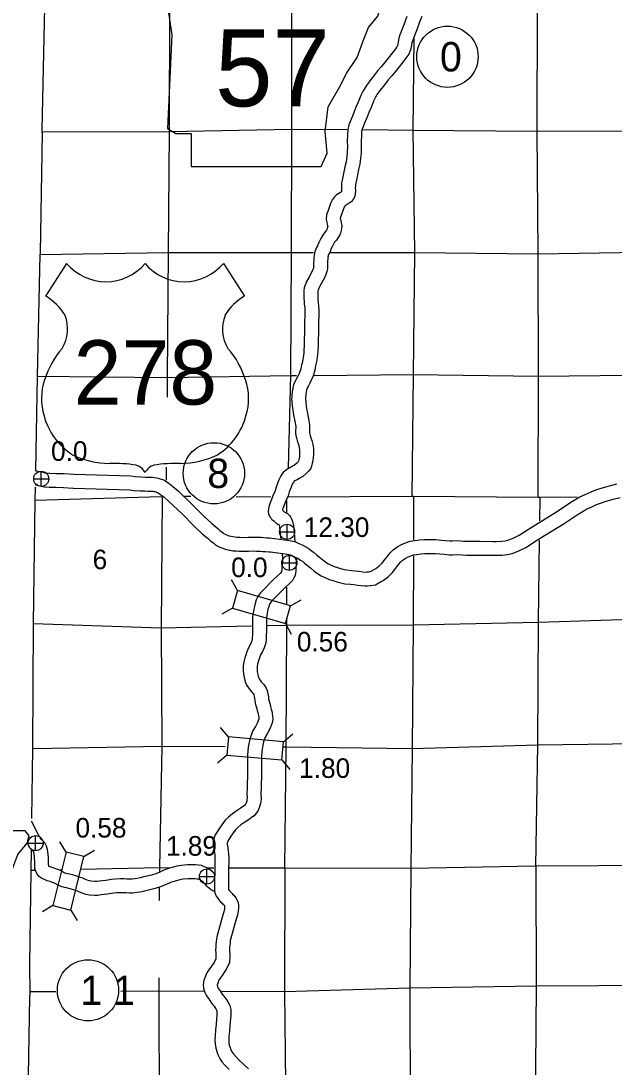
# Model space of a CAD drawing. Extents: x 369523 to 838377, y 495025 to 936819.
# Drawn here: x 574457 to 600020, y 546526 to 591641 of the extents above; entities that cross this region are included whole.
import ezdxf

# ---------------------------------------------------------------- set-up
doc = ezdxf.new("R2010")
doc.units = 0
for name, color, linetype in [('22', 7, 'Continuous'), ('6', 7, 'Continuous'), ('DSN_BRDG_Annotation', 7, 'Continuous'), ('DSN_DRFT_Common-Annotations', 7, 'Continuous'), ('DSN_DRFT_Common-Line', 7, 'Continuous'), ('DSN_DRFT_Junk-No-Plot', 7, 'Continuous'), ('Level 1', 7, 'Continuous'), ('Level 11', 7, 'Continuous'), ('Level 15', 7, 'Continuous'), ('Level 21', 7, 'Continuous'), ('Level 22', 7, 'Continuous'), ('Level 6', 7, 'Continuous')]:
    doc.layers.add(name, color=color, linetype=linetype)

msp = doc.modelspace()

# ---------------------------------------------------------------- linework, layer by layer
at = {"layer": '22'}
for points in [[(580555, 593710), (580954, 591045), (580777, 587004), (581132, 586782), (581798, 586782), (581798, 585361), (587394, 585361), (587660, 585938), (587571, 586871), (587704, 587937), (588193, 588780), (588504, 589402), (588948, 590068), (589214, 590779), (589436, 591356), (589836, 591845), (589925, 592155), (589747, 592377), (588371, 592377), (588681, 592999), (588726, 593399), (588542, 593706)], [(565448, 558052), (565848, 555387), (565670, 551346), (566025, 551124), (566691, 551124), (566691, 549703), (572287, 549703), (572554, 550280), (572465, 551213), (572598, 552279), (573086, 553122), (573397, 553744), (573841, 554410), (574108, 555121), (574330, 555698), (574730, 556187), (574818, 556498), (574641, 556720), (573264, 556720), (573575, 557341), (573619, 557741), (573435, 558048)]]:
    msp.add_lwpolyline(points, close=True, dxfattribs=at)
at = {"layer": '6'}
for p, q in [((576428, 581182), (575519, 579777)), ((583184, 581182), (584093, 579777))]:
    msp.add_line(p, q, dxfattribs=at)
for centre, radius, start, end in [((578120, 582606), 2211, 220.075, 319.6701), ((581492, 582606), 2211, 220.3299, 319.925), ((574332, 577737), 2361, 30.7809, 59.9883), ((585280, 577737), 2361, 120.0117, 149.2191), ((574852, 578359), 1618, 328.8105, 21.2108), ((584761, 578359), 1618, 158.7892, 211.1895), ((579084, 575042), 3776, 138.9565, 162.6913), ((580529, 575042), 3776, 17.3087, 41.0435), ((577837, 575351), 2495, 160.9576, 197.3819), ((581775, 575351), 2495, 342.6181, 19.0424), ((578243, 575358), 2887, 195.1074, 237.1312), ((581369, 575358), 2887, 302.8688, 344.8926), ((578297, 576267), 3707, 244.0771, 269.5779), ((578383, 565772), 6790, 81.1942, 90.9539), ((581230, 565772), 6790, 89.0461, 98.8058), ((581315, 576267), 3707, 270.4221, 295.9229), ((579232, 571860), 651, 28.0342, 72.9864), ((580381, 571860), 651, 107.0136, 151.9658)]:
    msp.add_arc(centre, radius, start, end, dxfattribs=at)
at = {"layer": 'DSN_DRFT_Common-Annotations'}
for p, q in [((575333, 571567), (575333, 572217)), ((575008, 571892), (575658, 571892)), ((585928, 569283), (585928, 569933)), ((585603, 569608), (586253, 569608)), ((586025, 567943), (586025, 568593)), ((585700, 568268), (586350, 568268)), ((575092, 555860), (575092, 556510)), ((574767, 556185), (575417, 556185)), ((582475, 554421), (582475, 555071)), ((582150, 554746), (582800, 554746))]:
    msp.add_line(p, q, dxfattribs=at)
for centre in [(575333, 571892), (585928, 569608), (586025, 568268), (575092, 556185), (582475, 554746)]:
    msp.add_circle(centre, 325, dxfattribs=at)
at = {"layer": 'DSN_DRFT_Common-Line'}
for centre in [(592840, 590097), (582773, 572133), (577347, 549836)]:
    msp.add_circle(centre, 1320, dxfattribs=at)
at = {"layer": 'Level 1'}
for points in [[(591087, 591834), (590957, 591469), (590873, 591264), (590826, 591147), (590785, 591037), (590743, 590894), (590723, 590809), (590694, 590645), (590680, 590587), (590666, 590544), (590649, 590511), (590602, 590439), (590342, 590108), (590113, 589814), (589989, 589663), (589824, 589483), (589612, 589202), (589451, 589002), (589315, 588819), (589204, 588632), (589105, 588421), (588991, 588140), (588898, 587923), (588804, 587686), (588741, 587534), (588595, 587164), (588545, 586964), (588530, 586738), (588519, 586449), (588526, 586227), (588520, 585988), (588501, 585797), (588468, 585571), (588423, 585346), (588380, 585129), (588330, 584919), (588296, 584773), (588279, 584655), (588270, 584555), (588268, 584433), (588274, 584339), (588272, 584305), (588271, 584292), (588268, 584272), (588234, 584249), (588064, 584142), (587967, 584054), (587880, 583938), (587802, 583765), (587692, 583460), (587666, 583396), (587627, 583297), (587619, 583080), (587637, 582960), (587661, 582879), (587672, 582825), (587681, 582774), (587681, 582771), (587676, 582754), (587656, 582684), (587652, 582674), (587620, 582617), (587578, 582555), (587476, 582434), (587383, 582259), (587324, 582144)], [(591730, 591832), (591649, 591625), (591518, 591255), (591429, 591038), (591386, 590931), (591355, 590847), (591323, 590741), (591311, 590690), (591282, 590521), (591257, 590423), (591224, 590317), (591169, 590210), (591090, 590088), (590814, 589738), (590582, 589441), (590443, 589270), (590286, 589099), (590085, 588833), (589925, 588634), (589815, 588486), (589735, 588352), (589656, 588181), (589545, 587908), (589453, 587694), (589361, 587462), (589298, 587309), (589167, 586979), (589140, 586870), (589129, 586707), (589119, 586447), (589126, 586229), (589119, 585950), (589097, 585724), (589060, 585469), (589012, 585228), (588966, 585000), (588914, 584781), (588886, 584662), (588875, 584587), (588870, 584523), (588868, 584448), (588876, 584338), (588870, 584263), (588868, 584225), (588856, 584147), (588833, 584061), (588791, 583956), (588692, 583837), (588567, 583749), (588427, 583661), (588412, 583648), (588400, 583632), (588359, 583540), (588252, 583246), (588223, 583174), (588223, 583172), (588221, 583113), (588224, 583092), (588244, 583025), (588262, 582935), (588282, 582818), (588279, 582692), (588256, 582597), (588225, 582494), (588198, 582420), (588131, 582301), (588057, 582193), (587976, 582096), (587915, 581982), (587859, 581872)], [(587321, 582136), (587269, 582027), (587234, 581945), (587198, 581870), (587164, 581798), (587128, 581700), (587108, 581614), (587094, 581533), (587082, 581430), (587074, 581328), (587070, 581202), (587073, 581099), (587075, 581048), (587073, 581029), (587065, 580983), (587043, 580921), (587023, 580874), (586955, 580744), (586890, 580625), (586808, 580478), (586770, 580402), (586730, 580318), (586691, 580218), (586666, 580124), (586651, 580019), (586651, 579920), (586650, 579866), (586650, 579779), (586653, 579675), (586658, 579556), (586670, 579420), (586692, 579279), (586699, 579177), (586676, 578430), (586664, 577660), (586654, 577414), (586646, 577331), (586633, 577230), (586614, 577128), (586601, 577041), (586571, 576889), (586554, 576807), (586535, 576725), (586514, 576644), (586485, 576549), (586467, 576483), (586445, 576431), (586371, 576293), (586304, 576160), (586269, 576080), (586205, 575946), (586189, 575890), (586157, 575727), (586146, 575632), (586135, 575541), (586129, 575445), (586125, 575334), (586130, 575225), (586133, 575187), (586142, 575104), (586151, 575023), (586157, 574966), (586173, 574827), (586199, 574675), (586223, 574572), (586251, 574446), (586271, 574311), (586286, 574224), (586298, 574155), (586298, 574105), (586291, 573967), (586294, 573866), (586312, 573761), (586347, 573610), (586384, 573492), (586417, 573380), (586452, 573252), (586464, 573160), (586466, 573079), (586461, 572980), (586456, 572855), (586449, 572785), (586430, 572713), (586415, 572651), (586407, 572627), (586398, 572615), (586348, 572566), (586254, 572486), (586168, 572435), (586077, 572381), (585966, 572328), (585840, 572243), (585761, 572163), (585656, 572023), (585574, 571855), (585534, 571740), (585458, 571531), (585408, 571383), (585313, 571165), (585166, 570776), (585146, 570673)], [(587863, 581880), (587816, 581780), (587780, 581697), (587741, 581615), (587719, 581567), (587704, 581528), (587696, 581494), (587688, 581447), (587680, 581373), (587673, 581294), (587670, 581201), (587673, 581118), (587676, 581038), (587670, 580953), (587647, 580830), (587602, 580699), (587563, 580613), (587484, 580462), (587415, 580335), (587338, 580197), (587309, 580140), (587281, 580080), (587262, 580031), (587255, 580005), (587251, 579977), (587251, 579912), (587250, 579858), (587250, 579789), (587253, 579696), (587257, 579595), (587266, 579494), (587289, 579347), (587300, 579188), (587276, 578416), (587264, 577643), (587253, 577372), (587242, 577262), (587225, 577135), (587205, 577028), (587192, 576938), (587159, 576773), (587141, 576679), (587117, 576580), (587091, 576481), (587061, 576383), (587036, 576288), (586987, 576172), (586903, 576016), (586847, 575904), (586815, 575831), (586770, 575737), (586750, 575634), (586742, 575564), (586733, 575487), (586728, 575415), (586726, 575338), (586729, 575262), (586731, 575240), (586739, 575167), (586747, 575088), (586753, 575033), (586767, 574911), (586787, 574794), (586808, 574706), (586841, 574555), (586863, 574406), (586877, 574329), (586898, 574209), (586899, 574091), (586892, 573961), (586893, 573925), (586900, 573879), (586926, 573769), (586958, 573667), (586995, 573543), (587042, 573371), (587063, 573207), (587067, 573071), (587061, 572954), (587055, 572810), (587040, 572676), (587012, 572567), (586992, 572485), (586945, 572344), (586850, 572219), (586753, 572123), (586604, 571997), (586474, 571919), (586358, 571851), (586265, 571806), (586225, 571779), (586216, 571770), (586170, 571709), (586129, 571623), (586099, 571538), (586024, 571333), (585968, 571167), (585870, 570939), (585745, 570610), (585734, 570556)], [(585147, 570681), (585130, 570603), (585119, 570496), (585133, 570370), (585203, 570241), (585235, 570196), (585275, 570143), (585351, 570076), (585445, 569995), (585526, 569944), (585570, 569919), (585583, 569900), (585589, 569883), (585601, 569827), (585607, 569789), (585617, 569698), (585655, 569296)], [(585732, 570548), (585731, 570541), (585744, 570529), (585803, 570478), (585835, 570458), (585893, 570425), (585943, 570393), (586023, 570322), (586068, 570254), (586120, 570175), (586166, 570053), (586191, 569936), (586202, 569866), (586214, 569757), (586268, 569186)], [(585710, 568673), (585730, 568425), (585725, 568365), (585724, 568288), (585715, 568208), (585705, 568090), (585702, 567983), (585694, 567905), (585682, 567882), (585675, 567870), (585643, 567833), (585353, 567561), (584848, 567048), (584787, 566976), (584691, 566861), (584635, 566763), (584601, 566669), (584569, 566572), (584517, 566392), (584497, 566269), (584470, 566108), (584444, 565948), (584437, 565831), (584440, 565675), (584441, 565507), (584434, 565331), (584433, 565167), (584430, 565020), (584423, 564948), (584382, 564833), (584322, 564707), (584242, 564547), (584179, 564395), (584144, 564294), (584100, 564172), (584064, 564006), (584041, 563848), (584035, 563614), (584051, 563482), (584074, 563337), (584107, 563199), (584140, 563106), (584200, 562979), (584267, 562876), (584336, 562774), (584416, 562684), (584459, 562641), (584460, 562640), (584488, 562593), (584501, 562566), (584514, 562513), (584524, 562430), (584536, 562324), (584565, 562166), (584607, 562026), (584643, 561908), (584666, 561824), (584681, 561754), (584694, 561679), (584708, 561596), (584709, 561550), (584707, 561536), (584646, 561386), (584563, 561220), (584437, 561010), (584340, 560716), (584298, 560544), (584255, 560327), (584226, 559992), (584224, 559688), (584226, 559381), (584219, 559081), (584213, 558720), (584209, 558545), (584197, 558345), (584206, 558122), (584199, 558063), (584187, 557997), (584178, 557950), (584151, 557880), (584138, 557862), (584096, 557811), (584046, 557776), (583913, 557675), (583776, 557589), (583577, 557447), (583405, 557309), (583264, 557176), (583113, 556972), (583011, 556822), (582910, 556667), (582832, 556539), (582772, 556384), (582749, 556254), (582747, 556117), (582764, 555970), (582787, 555865), (582800, 555770), (582811, 555672), (582817, 555501)], [(586328, 568476), (586331, 568426), (586325, 568337), (586323, 568251), (586313, 568150), (586304, 568055), (586301, 567942), (586286, 567804), (586262, 567702), (586207, 567589), (586159, 567512), (586076, 567417), (585772, 567132), (585290, 566642), (585244, 566588), (585186, 566518), (585182, 566512), (585168, 566473), (585142, 566394), (585103, 566260), (585089, 566171), (585062, 566011), (585041, 565882), (585037, 565819), (585040, 565682), (585041, 565497), (585034, 565317), (585033, 565159), (585029, 564986), (585013, 564817), (584937, 564603), (584862, 564444), (584788, 564298), (584740, 564181), (584709, 564093), (584678, 564007), (584655, 563899), (584640, 563797), (584636, 563642), (584645, 563566), (584663, 563454), (584684, 563368), (584696, 563334), (584725, 563272), (584767, 563207), (584811, 563142), (584851, 563097), (584905, 563044), (584952, 562985), (585021, 562872), (585069, 562764), (585105, 562624), (585120, 562499), (585130, 562412), (585149, 562307), (585181, 562199), (585219, 562076), (585249, 561968), (585270, 561870), (585286, 561777), (585306, 561652), (585310, 561513), (585289, 561375), (585192, 561139), (585089, 560931), (584986, 560759), (584917, 560552), (584884, 560415), (584850, 560242), (584826, 559964), (584824, 559687), (584826, 559376), (584819, 559070), (584813, 558707), (584808, 558520), (584798, 558340), (584808, 558097), (584792, 557972), (584777, 557889), (584758, 557788), (584683, 557589), (584612, 557494), (584507, 557365), (584398, 557290), (584256, 557181), (584110, 557089), (583939, 556968), (583800, 556856), (583714, 556776), (583603, 556625), (583510, 556489), (583417, 556347), (583372, 556273), (583353, 556224), (583349, 556197), (583348, 556146), (583357, 556069), (583378, 555969), (583395, 555844), (583409, 555717), (583417, 555524)], [(582794, 554863), (582718, 554941), (582576, 555056), (582443, 555131), (582363, 555167), (582239, 555212), (582109, 555232), (581978, 555241), (581629, 555241), (581380, 555226), (581174, 555194), (581036, 555153), (580860, 555099), (580694, 555040), (580593, 555000), (580439, 554932), (580272, 554865), (580078, 554804), (579756, 554727), (579597, 554691), (579467, 554663), (579368, 554643), (579246, 554628), (579156, 554629), (579020, 554636), (578907, 554641), (578744, 554643), (578527, 554635), (578365, 554616), (578113, 554576), (577975, 554560), (577846, 554543), (577732, 554530), (577644, 554528), (577490, 554537), (577409, 554555), (577309, 554584), (577236, 554616), (577129, 554667), (577014, 554706), (576915, 554738), (576866, 554755), (576684, 554810), (576552, 554842), (576466, 554860), (576406, 554875), (576350, 554894), (576304, 554917), (576296, 554922), (576223, 554968), (576088, 555030), (575963, 555076), (575890, 555097), (575802, 555127), (575723, 555158), (575667, 555180), (575663, 555183), (575655, 555210), (575650, 555282), (575651, 555375), (575648, 555557), (575635, 555699), (575616, 555830), (575596, 555915), (575582, 555959), (575554, 556058), (575486, 556190), (575410, 556265), (575338, 556344), (575293, 556406), (575240, 556492), (575211, 556538), (574908, 557135)], [(582804, 554097), (582713, 554138), (582655, 554175), (582580, 554226), (582529, 554268), (582469, 554325), (582413, 554393), (582312, 554498), (582238, 554558), (582174, 554594), (582138, 554610), (582089, 554628), (582043, 554635), (581958, 554641), (581647, 554641), (581444, 554629), (581306, 554607), (581208, 554578), (581049, 554530), (580907, 554479), (580824, 554446), (580671, 554379), (580474, 554300), (580238, 554226), (579893, 554143), (579727, 554105), (579590, 554076), (579465, 554050), (579279, 554027), (579137, 554029), (578989, 554036), (578890, 554041), (578753, 554042), (578573, 554036), (578447, 554021), (578195, 553982), (578049, 553964), (577919, 553947), (577773, 553931), (577633, 553928), (577407, 553941), (577260, 553973), (577103, 554019), (576987, 554070), (576902, 554110), (576824, 554137), (576727, 554169), (576683, 554183), (576525, 554231), (576420, 554257), (576334, 554275), (576238, 554299), (576118, 554339), (576015, 554391), (575983, 554410), (575936, 554439), (575858, 554476), (575778, 554505), (575711, 554524), (575595, 554564), (575501, 554600), (575400, 554641), (575321, 554688), (575248, 554739), (575152, 554848), (575100, 554971), (575062, 555103), (575050, 555263), (575051, 555374), (575048, 555525), (575039, 555628), (575026, 555717), (575017, 555755), (575007, 555787), (574995, 555832), (574976, 555850), (574911, 555922)], [(582817, 555517), (582814, 555318), (582807, 555177), (582800, 554355), (582801, 554109), (582825, 554016), (582873, 553892), (582922, 553822), (582988, 553739), (583063, 553653), (583123, 553595), (583161, 553552), (583199, 553517), (583224, 553488), (583233, 553465), (583234, 553458), (583235, 553414), (583235, 553404), (583231, 553356), (583203, 553215), (583148, 553027), (582896, 552141), (582885, 552052), (582872, 551930), (582860, 551832), (582853, 551752), (582851, 551691), (582845, 551575), (582851, 551460), (582861, 551375), (582861, 551367), (582863, 551320), (582860, 551250), (582854, 551189)], [(583417, 555508), (583414, 555298), (583407, 555159), (583400, 554354), (583401, 554191), (583406, 554177), (583448, 554125), (583498, 554067), (583559, 554009), (583594, 553969), (583632, 553933), (583674, 553884), (583740, 553815), (583816, 553620), (583832, 553512), (583835, 553427), (583835, 553377), (583825, 553269), (583786, 553073), (583724, 552860), (583486, 552023), (583481, 551984), (583468, 551861), (583457, 551770), (583452, 551718), (583451, 551667), (583446, 551575), (583449, 551509), (583461, 551410), (583461, 551382), (583463, 551321), (583459, 551207), (583451, 551127), (583443, 551038)], [(582853, 551188), (582783, 551033), (582742, 550977), (582671, 550872), (582562, 550726), (582472, 550589), (582407, 550450), (582386, 550377), (582344, 550273), (582325, 550171), (582317, 550072), (582327, 549935), (582354, 549827), (582386, 549738), (582438, 549622), (582477, 549555), (582554, 549465), (582640, 549326), (582730, 549212), (582787, 549150), (582828, 549087), (582859, 549039), (582891, 548976), (582902, 548934), (582900, 548788), (582867, 548370), (582842, 548135), (582824, 547873), (582820, 547721), (582824, 547527), (582850, 547343), (582908, 547158), (582947, 547067), (583025, 546900), (583119, 546752), (583274, 546579), (583427, 546421)], [(583442, 551037), (583304, 550729), (583232, 550631), (583160, 550525), (583053, 550381), (582997, 550296), (582971, 550240), (582954, 550181), (582922, 550102), (582920, 550091), (582919, 550071), (582922, 550031), (582929, 550002), (582943, 549962), (582971, 549901), (583041, 549819), (583132, 549671), (583187, 549602), (583264, 549518), (583332, 549412), (583380, 549339), (583456, 549188), (583503, 549005), (583500, 548761), (583465, 548315), (583440, 548082), (583424, 547844), (583420, 547719), (583423, 547576), (583438, 547475), (583472, 547366), (583495, 547312), (583553, 547189), (583600, 547115), (583713, 546988), (583852, 546845), (584070, 546631), (584262, 546456)]]:
    msp.add_lwpolyline(points, dxfattribs=at)
at = {"layer": 'Level 11'}
for points in [[(575066, 572254), (575120, 572244), (575201, 572231), (575372, 572193), (575487, 572156), (575538, 572148), (575699, 572135), (575966, 572129), (576313, 572125), (576752, 572097)], [(576742, 572097), (579197, 572021), (579382, 571995), (579637, 571978), (579824, 571971), (579934, 571966), (580023, 571967), (580124, 571963), (580210, 571956), (580301, 571943), (580371, 571925), (580460, 571901), (580572, 571861), (580658, 571817), (580750, 571760), (580846, 571693), (580994, 571581), (581244, 571359), (581810, 570822), (582347, 570281), (582667, 569981), (582857, 569826), (582944, 569749), (583032, 569671), (583124, 569599), (583186, 569549), (583221, 569526), (583285, 569493), (583367, 569459), (583420, 569440), (583519, 569418), (583671, 569390), (583768, 569381), (583892, 569378), (584018, 569371), (584245, 569380), (584438, 569382), (584623, 569381), (584809, 569373), (584926, 569363), (585039, 569354), (585177, 569343), (585275, 569337), (585386, 569325), (586029, 569240)], [(575079, 571643), (575089, 571641), (575217, 571613), (575345, 571572), (575462, 571552), (575669, 571535), (575957, 571529), (576290, 571526), (576713, 571498)], [(586026, 569241), (586171, 569210), (586251, 569187), (586354, 569145), (586436, 569106), (586571, 569045), (586701, 568974), (586831, 568898), (586964, 568809), (587060, 568729), (587197, 568620), (587326, 568509), (587464, 568394), (587582, 568309), (587687, 568241), (587805, 568184), (587961, 568120), (588095, 568073), (588236, 568029), (588385, 567989), (588510, 567963), (588717, 567942), (588869, 567926), (589035, 567905), (589192, 567886), (589290, 567876), (589364, 567881), (589455, 567885), (589516, 567897), (589646, 567974), (589757, 568026), (589901, 568140), (590021, 568257), (590143, 568410), (590235, 568525), (590368, 568696), (590498, 568828), (590707, 568978), (590861, 569056), (591037, 569134), (591233, 569200), (591433, 569231), (591631, 569262), (591841, 569275), (592096, 569278), (592337, 569278), (592575, 569251), (592745, 569237), (592946, 569223), (593046, 569222), (593277, 569234), (593531, 569209), (593679, 569199), (593991, 569199), (594246, 569209), (594789, 569198), (594955, 569197), (595165, 569204), (595323, 569218), (595440, 569249), (595598, 569308), (595673, 569340), (595925, 569462), (596451, 569798), (597546, 570472), (598157, 570881), (598547, 571119), (598781, 571224), (599037, 571340), (599239, 571413), (599462, 571485), (599830, 571592), (600144, 571672)], [(576723, 571497), (579146, 571423), (579321, 571398), (579606, 571379), (579800, 571372), (579922, 571366), (580013, 571367), (580088, 571364), (580142, 571359), (580184, 571353), (580221, 571344), (580281, 571328), (580333, 571309), (580364, 571294), (580420, 571259), (580493, 571208), (580614, 571116), (580838, 570917), (581391, 570393), (581929, 569851), (582272, 569529), (582468, 569370), (582546, 569300), (582647, 569210), (582752, 569128), (582831, 569066), (582913, 569010), (583033, 568948), (583152, 568899), (583255, 568862), (583400, 568830), (583589, 568795), (583732, 568782), (583868, 568778), (584014, 568771), (584259, 568780), (584438, 568782), (584610, 568781), (584772, 568774), (584876, 568765), (584991, 568756), (585136, 568744), (585223, 568739), (585312, 568729), (585950, 568645)], [(585926, 568649), (586024, 568628), (586053, 568620), (586114, 568595), (586185, 568562), (586303, 568508), (586405, 568452), (586512, 568390), (586604, 568328), (586681, 568264), (586813, 568158), (586938, 568051), (587097, 567919), (587244, 567813), (587392, 567718), (587559, 567636), (587748, 567559), (587907, 567503), (588070, 567452), (588246, 567406), (588418, 567369), (588655, 567345), (588800, 567330), (588961, 567310), (589125, 567290), (589279, 567274), (589397, 567282), (589527, 567287), (589733, 567329), (589926, 567443), (590075, 567512), (590297, 567689), (590467, 567854), (590612, 568036), (590706, 568154), (590820, 568301), (590889, 568370), (591019, 568463), (591119, 568514), (591255, 568575), (591375, 568615), (591526, 568638), (591696, 568665), (591863, 568675), (592099, 568678), (592303, 568678), (592517, 568654), (592699, 568639), (592922, 568623), (593058, 568622), (593264, 568632), (593482, 568611), (593658, 568599), (594002, 568599), (594251, 568609), (594781, 568598), (594963, 568597), (595201, 568605), (595427, 568625), (595622, 568676), (595819, 568751), (595920, 568793), (596219, 568938), (596769, 569290), (597871, 569967), (598480, 570375), (598827, 570587), (599028, 570677), (599264, 570784), (599433, 570845), (599638, 570912), (599988, 571013), (600286, 571089)]]:
    msp.add_lwpolyline(points, dxfattribs=at)
at = {"layer": 'Level 15'}
for points in [[(580520, 571122), (575060, 570958)], [(581785, 571133), (581511, 571135)], [(585229, 571106), (583738, 571118)], [(598434, 571106), (596831, 571088), (596747, 571094), (591383, 571130), (591311, 571132), (585972, 571101)]]:
    msp.add_lwpolyline(points, dxfattribs=at)
at = {"layer": 'Level 21'}
for p, q in [((583790, 567077), (583535, 567540)), ((586073, 566419), (586535, 566675)), ((583571, 566316), (583109, 566061)), ((585854, 565658), (586109, 565196)), ((583401, 560761), (583061, 561165)), ((585768, 560558), (586172, 560898)), ((583333, 559972), (582929, 559632)), ((585701, 559769), (586041, 559365)), ((576407, 555793), (576134, 556246)), ((577175, 555603), (577628, 555875)), ((575834, 553488), (575382, 553215)), ((576603, 553297), (576875, 552844))]:
    msp.add_line(p, q, dxfattribs=at)
for points in [[(586073, 566419), (583790, 567077), (583571, 566316), (585854, 565658)], [(583333, 559972), (585701, 559769), (585768, 560558), (583401, 560761)], [(576603, 553297), (577175, 555603), (576407, 555793), (575834, 553488)]]:
    msp.add_lwpolyline(points, close=True, dxfattribs=at)
at = {"layer": 'Level 22'}
for points in [[(580858, 597511), (580863, 592205), (580846, 586878), (580805, 581651), (580764, 576264), (580754, 575409)], [(585986, 572369), (586083, 576346), (586119, 581651), (586131, 586979), (586129, 592262), (586193, 597512)], [(596747, 571094), (596757, 576326), (596745, 581591), (596707, 586889), (596719, 592176), (596719, 597546)], [(591395, 590889), (591353, 586932), (591413, 581648), (591363, 576395), (591311, 571132)], [(580846, 586878), (586131, 586979), (588499, 586958)], [(589185, 586952), (591353, 586932), (596707, 586889), (601999, 586904), (607544, 587007)], [(575350, 586852), (580846, 586878)], [(575288, 581567), (580805, 581651)], [(580805, 581651), (586119, 581651), (587071, 581650)], [(587785, 581650), (591413, 581648), (596745, 581591), (602035, 581680), (607517, 581710)], [(575161, 576318), (580764, 576264), (586083, 576346), (586327, 576348)], [(587100, 576355), (591363, 576395), (596757, 576326), (602071, 576382), (607489, 576436)], [(580717, 572390), (580710, 571831)], [(580543, 571123), (580507, 565465), (580525, 560365), (580424, 555112)], [(585912, 570446), (585912, 570956)], [(591383, 571130), (591376, 569265)], [(596819, 570080), (596831, 571088)], [(596644, 555197), (596732, 560424), (596766, 565719), (596809, 569249)], [(591373, 568580), (591361, 565603), (591325, 560264), (591267, 555083)], [(585918, 566481), (585917, 567224)], [(585087, 565567), (585919, 565585), (591361, 565603), (596766, 565719), (602141, 565881), (607311, 565847)], [(585826, 555104), (585895, 560330), (585919, 565585), (585918, 565854)], [(574979, 565662), (580507, 565465)], [(580507, 565465), (584401, 565552)], [(574979, 560270), (580525, 560365)], [(580525, 560365), (583254, 560347)], [(585761, 560331), (585895, 560330), (591325, 560264), (596732, 560424), (602108, 560492), (607275, 560546)], [(575057, 555001), (574899, 554997)], [(576187, 555024), (576151, 555023)], [(580841, 555111), (580424, 555112), (577032, 555042)], [(580424, 555112), (580424, 554965)], [(582765, 555108), (582517, 555109)], [(607253, 555266), (602030, 555217), (596644, 555197), (591267, 555083), (585826, 555104), (583428, 555107)], [(585826, 555104), (585821, 549773), (585878, 544485), (585867, 543180)], [(591267, 555083), (591213, 549925), (591236, 544647), (591217, 539245)], [(596644, 555197), (596660, 550018), (596613, 544678), (596605, 539336)], [(580421, 554258), (580418, 553704)], [(580404, 550380), (580401, 549793), (580414, 544480), (580344, 539155)], [(607221, 549875), (602083, 550041), (596660, 550018), (591213, 549925), (585821, 549773), (583113, 549783)], [(575965, 549773), (574833, 549768)], [(582337, 549786), (580401, 549793), (578764, 549785)]]:
    msp.add_lwpolyline(points, dxfattribs=at)
at = {"layer": 'Level 6'}
for points in [[(575455, 596456), (575475, 592233), (575354, 586966), (575366, 586815), (575282, 581620), (575279, 581563), (575161, 576318), (575084, 572254)], [(575071, 571528), (575060, 570958), (574979, 565662), (574952, 560258), (574915, 557250)], [(574899, 555894), (574888, 554961), (574821, 550970)], [(574821, 550970), (574837, 549703), (574826, 549545), (574743, 544452), (574742, 544314), (574640, 539047), (574618, 533995), (574605, 533769), (571248, 533702)]]:
    msp.add_lwpolyline(points, dxfattribs=at)

# ---------------------------------------------------------------- texts
at = {"layer": '22'}
msp.add_text('57', height=3326.4, dxfattribs=at).set_placement((582826, 587956))
at = {"layer": '6'}
msp.add_text('278', height=2772, dxfattribs=at).set_placement((576731, 575097))
at = {"layer": 'DSN_BRDG_Annotation'}
for s, p in [('0.0', (575755, 572668)), ('12.30', (586648, 569387)), ('0.0', (583517, 567655)), ('1.89', (580707, 555643))]:
    msp.add_text(s, height=844.8, dxfattribs=at).set_placement(p)
at = {"layer": 'DSN_DRFT_Common-Line'}
for s, height, p in [('0', 1267, (592517, 589463)), ('8', 1267, (582490, 571499)), ('1 1', 1267.2, (577017, 549203))]:
    msp.add_text(s, height=height, dxfattribs=at).set_placement(p)
at = {"layer": 'DSN_DRFT_Junk-No-Plot'}
for s, p in [('0.56', (586349, 564448)), ('1.80', (586448, 558996)), ('0.58', (576809, 556424))]:
    msp.add_text(s, height=844.8, dxfattribs=at).set_placement(p)
at = {"layer": 'Level 22'}
msp.add_text('6', height=845, dxfattribs=at).set_placement((577547, 567995))

doc.saveas('drawing.dxf')
